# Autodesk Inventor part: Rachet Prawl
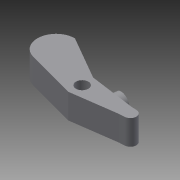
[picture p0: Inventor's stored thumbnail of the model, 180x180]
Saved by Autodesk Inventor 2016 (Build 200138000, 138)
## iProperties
Created: 2013-11
Part Number: Rachet Prawl
Material: Generic
Document SubType Name: Modeling
Designer: 603839
Density: 1 g/cm^3
Appearance: Default
Mass: 7.3567 g
Surface Area: 30.8961 cm^2
Volume: 7.3567 cm^3
Author: 603839
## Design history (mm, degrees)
sketch "Sketch7"
  geometry: L1 (25.4, -6.35)-(0.002, -3.175); L2 (25.4, 6.35)-(0, 3.175); L3 (25.4, -6.35)-(49.935, -12.924); L4 (25.4, 6.35)-(49.935, -0.224); L5 (25.4, 6.35)-(50.8, 6.35); A1 r 3.175 centre (0, 0) between (0, 3.175) and (0.002, -3.175); A2 r 6.574 centre (48.233, -6.574) between (49.935, -12.924) and (49.935, -0.224); 1 further point
  constraints: 10 end point, 4 point on circle, 2 centre point, 1 coincident, 1 equal length, 1 horizontal, 1 parallel, 1 tangent
  dimensions: "d13" = 6.35 diameter of A1; "d25" = 25.4 distance of L1.start L3.end; "d27" = 25.4 distance of L2.start L4.end; "d28" = 15 deg angle of L4 L5 (derived)
extrude "Extrusion5" new body sketch "Sketch7" distance "d19" = 12.7; taper "d20" = 0 deg
hole "Hole1" diameter "d31" = 6.35; stored, may be unused: countersink angle "d35" = 82 deg, drill point angle "d37" = 118 deg; dims "d29" = 6.35, "d30" = 25.4, "d32" = 19.05, "d33" = 9.525, "d34" = 6.35, "d36" = 25.4
sketch "Sketch8"
  geometry: L1 (-0.002, 3.175)-(-25.4, 6.35) reference; L2 (-25.4, -6.35)-(0, -3.175) reference; L3 (-0.002, 3.175)-(-2.522, 3.49); L4 (-0.002, 3.175)-(-2.542, 3.175); L5 (0, -3.175)-(-2.54, -3.175); L6 (-2.54, -3.175)-(-25.4, -6.35); L7 (-2.542, 3.175)-(-25.4, 6.35); A1 r 3.175 centre (0, 0) between (0, -3.175) and (-0.002, 3.175) reference
  constraints: 10 end point, 1 horizontal, 1 parallel, 1 point on line, 1 tangent
  dimensions: "d39" = 2.54 distance of L1.start L4.end; "d40" = 2.54 distance of L2.end L5.end
extrude "Extrusion6" cut sketch "Sketch8" stored distance "d41" = 6.35; taper "d42" = 0 deg
sketch "Sketch10"
  geometry: L1 (0, 0)-(0, 12.7) reference; L2 (0, 6.35)-(6.35, 6.35); C1 r 5.715 at (6.35, 6.35); 1 further point
  constraints: 2 end point, 1 centre point, 1 coincident, 1 midpoint, 1 perpendicular
  dimensions: "d47" = 6.35 distance of L2.start L2.end; "d48" = 11.43 diameter of C1
extrude "Extrusion8" cut sketch "Sketch10" distance "d49" = 6.35; taper "d50" = 0 deg
sketch "Sketch11"
  geometry: L1 (-25.4, -6.35)-(-2.54, -3.175) reference; L2 (-2.54, -3.175)-(0, -3.175) reference; L3 (-0.002, 3.175)-(-2.542, 3.175) reference; L4 (-2.542, 3.175)-(-25.4, 6.35) reference; L5 (-25.4, 6.35)-(-49.935, 12.924) reference; L6 (-49.935, 0.224)-(-25.4, -6.35) reference; L7 (-25.4, 6.35)-(-47.397, 19.05); L8 (-25.4, 6.35)-(0, 6.35); A1 r 3.175 centre (0, 0) between (0, -3.175) and (-0.002, 3.175) reference; A2 r 6.574 centre (-48.233, 6.574) between (-49.935, 12.924) and (-49.935, 0.224) reference; A3 r 9.576 centre (-47.456, 9.474) between (-47.397, 19.05) and (-49.935, 0.224)
  constraints: 4 end point, 2 point on circle, 1 centre point, 1 equal length, 1 horizontal, 1 tangent
  dimensions: "d51" = 25.4 distance of L4.end L7.end; "d52" = 150 deg angle of L8 L7
extrude "Extrusion9" join sketch "Sketch11" stored distance "d53" = 25.4; taper "d54" = 0 deg
sketch "Sketch12"
  geometry: L1 (-2.54, -3.175)-(0, -3.175) reference; L2 (-0.002, 3.175)-(-2.542, 3.175) reference; L3 (-2.542, 3.175)-(0, 3.048); L4 (-2.54, -3.175)-(0, -3.048); A1 r 3.175 centre (0, 0) between (0, -3.175) and (-0.002, 3.175) reference; A2 r 3.048 centre (0, 0) between (0, -3.048) and (0, 3.048)
  constraints: 4 end point, 2 point on circle, 1 centre point, 1 coincident
  dimensions: "d55" = 6.096 diameter of A2
extrude "Extrusion10" cut sketch "Sketch12" distance "d56" = 25.4; taper "d57" = 0 deg
sketch "Sketch13"
  geometry: C1 r 5.715 at (0, 0) reference; 1 further point
extrude "Extrusion11" join sketch "Sketch13" stored distance "d58" = 25.4; taper "d59" = 0 deg
sketch "Sketch14"
  geometry: C1 r 4.445 at (-11.539, 6.35); 1 further point
  constraints: 1 centre point
  dimensions: "d60" = 8.89 diameter of C1
extrude "Extrusion12" join sketch "Sketch14" distance "d61" = 4.445; taper "d62" = 0 deg
body "Solid2"
